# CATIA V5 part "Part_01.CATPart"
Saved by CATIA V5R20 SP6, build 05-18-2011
Part number: Part_01
Bounding box of the stored display mesh (mm): x -7 to 7, y -40 to 5.995, z -22 to 5.999
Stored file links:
  E:\#01 CATIA Lecture Materials\#16 3D Print Test\3D Print Test\7th Test\Part_01.CATPart
  E:\#01 CATIA Lecture Materials\#16 3D Print Test\3D Print Test\7th Test\Part_02.CATPart
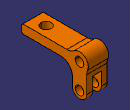
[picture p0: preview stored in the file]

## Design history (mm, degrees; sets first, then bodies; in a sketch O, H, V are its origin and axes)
Set1 "Reference Data"
  Point1 "Center Point": (0, 0, 0)
Body1 (main body)
  Sketch1 on yz-plane, origin (0, 0, 0), H (0, 1, 0), V (0, 0, 1)
    line L1 (-5.1962, 3) -> (-40, 3)
    line L2 (-40, 3) -> (-40, -3)
    line L3 (-40, -3) -> (-5, -3)
    line L4 (5, -3.3166) -> (5, -17)
    construction line L5 (5, -17) -> (-5, -17)
    line L6 (-5, -17) -> (-5, -3)
    arc A1 centre (0, 0) radius 6 from (5, -3.3166) to (-5.1962, 3) ccw
    arc A2 centre (0, -17) radius 5 from (-5, -17) to (5, -17) ccw
    distance L2 V = 40
    distance L1 L3 = 6
    distance L3 L5 = 14
    distance L6 L4 = 10
    radius A1 = 6
    horizontal: L1 H, L3 H, L5 H
    vertical: L2 V, L4 V, L6 V
    symmetry: L1 L3 H, L6 L4 V
    tangency: A2 L4
  Pad1: profile Sketch1, direction (-1, 0, 0), length 7, mirrored extent
  Fillet1: radius 8, on edge [face of Pad1 from Sketch1.A1 | face of Pad1 from Sketch1.L1]
  Fillet2: radius 8, on edge [face of Pad1 from Sketch1.L3 | face of Pad1 from Sketch1.L6]
  Fillet3: radius 8, on edge [face of Pad1 from Sketch1.L4 | face of Pad1 from Sketch1.A1]
  Chamfer1: length 1, angle 45, on edge [face of Pad1 from Sketch1.L1 | face of Pad1 from Sketch1.L2]; edge [face of Pad1 from Sketch1.L2 | face of Pad1 from Sketch1.L3]
  Sketch2 on yz-plane, origin (0, 0, 0), H (0, 1, 0), V (0, 0, 1)
    circle A1 centre (0, -17) radius 3
    point P1 (0, -17)
    reference projected arc E1 centre (0, -17) radius 5 from (-5, -17) to (5, -17) ccw from edge [face of Pad1 from Sketch1.A2 | start face of Pad1]
    radius A1 = 3
    coincidence: P1 V
    concentricity: P1 E1
  Pocket1: profile Sketch2, direction (-1, 0, 0), through (limit type 6), opposite side through (limit type 6)
  Sketch3 on face of Pad1 from Sketch1.L4, origin (0, 5, 0), H (-1, 0, 0), V (0, 0, 1)
    line L1 (0, -8) -> (0, -22)
    point P1 (0, -8)
    point P2 (0, -22)
    reference projected line E1 (7, -22) -> (-7, -22) from face of Pad1 from Sketch1.A2
    distance P1 P2 = 14
    coincidence: P1 V, P2 E1
    vertical: L1 V
  Pocket2: profile Sketch3, direction (0, -1, 0), through (limit type 6), thin wall 6
  Sketch4 on end face of Pad1, origin (-7, 0, 0), H (0, -1, 0), V (0, 0, 1)
    circle A1 centre (0, 0) radius 4
    radius A1 = 4
  Pocket3: profile Sketch4, direction (1, 0, 0), length 4
  Sketch5 on start face of Pad1, origin (7, 0, 0), H (0, 1, 0), V (0, 0, 1)
    circle A1 centre (0, 0) radius 3
    radius A1 = 3
  Pocket4: profile Sketch5, direction (-1, 0, 0), through (limit type 6)
  Sketch6 on face of Pad1 from Sketch1.L1, origin (0, 0, 3), H (0, 1, 0), V (-1, 0, 0)
    circle A1 centre (-30, 0) radius 3.5
    point P1 (-30, 0)
    reference projected line E1 (-40, -7) -> (-40, 7) from edge [face of Chamfer1 | face of Pad1 from Sketch1.L2]
    distance E1 P1 = 10
    radius A1 = 3.5
    coincidence: P1 H
  Pocket5: profile Sketch6, direction (0, 0, -1), through (limit type 6)
  Sketch7 on face of Pad1 from Sketch1.L1, origin (0, 0, 3), H (0, 1, 0), V (-1, 0, 0)
    polyline C1
    polyline C2
    polyline C3
    polyline C4
    point P1 (-13.2012, 3.542)
    point P6 (-13.2012, 3.542)
    coincidence: P1 P6
  Pocket6: profile Sketch7, direction (0, 0, -1), length 1, thin wall 1, deactivated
